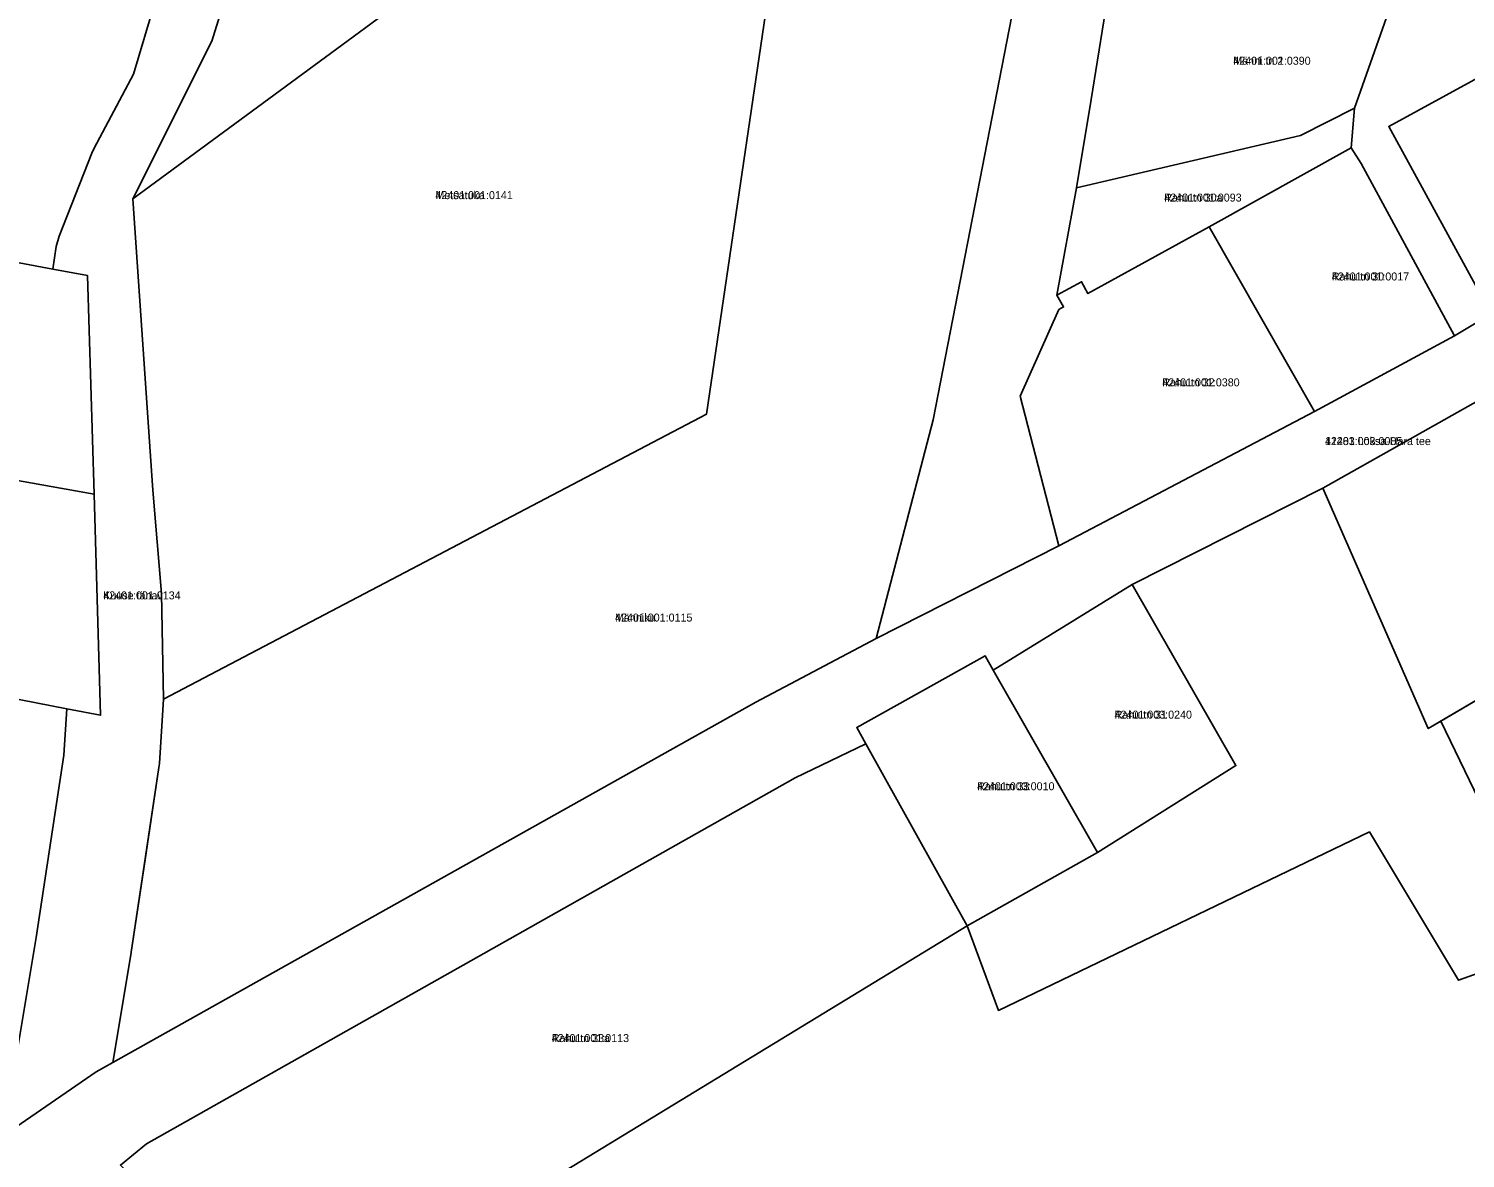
# Model space of a CAD drawing. Extents: x 595979 to 597983, y 6604231 to 6607350.
# Drawn here: x 596596.1 to 596865.4, y 6605070.1 to 6605281.9 of the extents above; entities that cross this region are included whole.
import ezdxf

# ---------------------------------------------------------------- set-up
doc = ezdxf.new("R2010")
doc.units = 0
for name, color, linetype in [('L_AADRESS', 7, 'Continuous'), ('PIIR', 7, 'Continuous'), ('TUNNUS', 7, 'Continuous')]:
    doc.layers.add(name, color=color, linetype=linetype)

msp = doc.modelspace()

# ---------------------------------------------------------------- linework, layer by layer
at = {"layer": 'PIIR'}
for points in [[(596829.27, 6605483.41), (596824.76, 6605453.75), (596820.25, 6605424.09), (596815.74, 6605394.45), (596814.19, 6605387.1), (596809.6, 6605357.21), (596804.47, 6605327.52), (596800, 6605298.23), (596795.25, 6605268.62), (596792.47, 6605252.09), (596788.8, 6605231.98), (596790.07, 6605229.75), (596789.19, 6605229.26), (596781.93, 6605213.04), (596789.19, 6605184.96), (596754.93, 6605167.57), (596765.64, 6605208.57), (596800.12, 6605385.84), (596804.06, 6605408.95), (596828.15, 6605567.17)], [(596647.27, 6605477.41), (596611.18, 6605411.05), (596610.56, 6605409.63), (596605.93, 6605395.9), (596605.48, 6605392.31), (596606.36, 6605381.09), (596607.07, 6605378.23), (596615.3, 6605359.14), (596622.82, 6605323.98), (596624.34, 6605313.37), (596622.34, 6605294.27), (596619.91, 6605287.47), (596619.75, 6605287), (596615.72, 6605273.39), (596608.35, 6605259.53), (596607.93, 6605258.6), (596601.78, 6605243.01), (596601.25, 6605241.06), (596600.61, 6605236.85), (596540.44, 6605248.17)], [(596877.22, 6605277.92), (596851, 6605263.59), (596870.21, 6605228.44), (596863.33, 6605224.33), (596845.82, 6605256.63), (596843.99, 6605259.57), (596844.57, 6605267.01), (596852.1, 6605288.33), (596859, 6605319.44), (596860.74, 6605348.98), (596864.82, 6605379.06), (596814.19, 6605387.1), (596815.74, 6605394.45), (596855.3, 6605388.41), (596859.8, 6605418.07), (596864.31, 6605447.73), (596868.82, 6605477.39)], [(596586.98, 6605071.41), (596608.69, 6605086.35), (596611.84, 6605088.12), (596732.37, 6605155.68), (596754.93, 6605167.57), (596789.19, 6605184.96), (596837.08, 6605210.13), (596863.33, 6605224.33), (596870.21, 6605228.44), (596896.56, 6605243.05), (596922.91, 6605257.44), (596948.6, 6605271.92), (596974.91, 6605286.34), (596986.01, 6605292.19), (596986.85, 6605290.66), (596994.62, 6605294.61), (597013.8, 6605306.51), (597040.14, 6605320.88), (597066.19, 6605334.9), (597093.1, 6605349.19), (597119.27, 6605363.58), (597145.51, 6605378.15), (597174.6, 6605393.75), (597194, 6605402.66)], [(597191.72, 6605387.01), (597156.63, 6605368.74), (597130.33, 6605354.15), (597103, 6605339.04), (597076.68, 6605324.49), (597050.42, 6605309.97), (597024.14, 6605295.52), (597016.87, 6605291.63), (597005.04, 6605285.24), (596978.08, 6605271.56), (596951.16, 6605258.14), (596927.39, 6605245.75), (596904.92, 6605232.87), (596881.66, 6605219.93), (596870.26, 6605213.58), (596838.64, 6605195.76), (596802.93, 6605177.68), (596776.88, 6605161.66), (596775.35, 6605164.36), (596751.28, 6605150.91), (596753, 6605147.82), (596739.75, 6605141.48), (596618.18, 6605072.86), (596613.27, 6605068.86)], [(596635.95, 6605297.46), (596630.39, 6605279.58), (596615.57, 6605250.02), (596619.36, 6605195.41), (596620.94, 6605176.05), (596621.36, 6605156.21), (596620.57, 6605144.18), (596620.49, 6605143.43), (596617.83, 6605125.72), (596615.29, 6605108.8), (596615.27, 6605108.65), (596611.84, 6605088.12), (596608.69, 6605086.35), (596586.98, 6605071.41)], [(596592.87, 6605083.8), (596597.5, 6605111.54), (596602.63, 6605145.74), (596603.2, 6605154.43), (596609.55, 6605153.19), (596608.32, 6605194.62), (596607.1, 6605235.63), (596600.61, 6605236.85), (596601.25, 6605241.06), (596601.78, 6605243.01), (596607.93, 6605258.6), (596608.35, 6605259.53), (596615.72, 6605273.39), (596619.75, 6605287)], [(596927.46, 6605126.04), (596864.06, 6605103.52), (596847.38, 6605131.33), (596777.85, 6605097.85), (596772.01, 6605113.71), (596796.42, 6605127.47), (596822.37, 6605143.75), (596802.93, 6605177.68), (596838.64, 6605195.76), (596858.43, 6605150.7), (596860.75, 6605152.06), (596874.19, 6605124.28)]]:
    msp.add_lwpolyline(points, dxfattribs=at)
for points in [[(596636.26, 6605434.88), (596804.06, 6605408.95), (596800.12, 6605385.84), (596781.86, 6605372.4), (596701.75, 6605313.42), (596615.57, 6605250.02), (596630.39, 6605279.58), (596635.95, 6605297.46), (596636.74, 6605309.9), (596630.78, 6605339.55), (596625.88, 6605356.1), (596620.85, 6605368.15), (596618.6, 6605376.49), (596619.44, 6605389.57), (596622.31, 6605405.35), (596625.22, 6605413.29)], [(596611.84, 6605088.12), (596615.27, 6605108.65), (596615.29, 6605108.8), (596620.49, 6605143.43), (596620.57, 6605144.18), (596621.36, 6605156.21), (596723.1, 6605209.62), (596742.88, 6605343.7), (596781.86, 6605372.4), (596800.12, 6605385.84), (596765.64, 6605208.57), (596754.93, 6605167.57), (596732.37, 6605155.68)], [(596701.75, 6605313.42), (596742.88, 6605343.7), (596723.1, 6605209.62), (596621.36, 6605156.21), (596620.94, 6605176.05), (596619.36, 6605195.41), (596615.57, 6605250.02)], [(596800, 6605298.23), (596839.35, 6605290.97), (596852.1, 6605288.33), (596844.57, 6605267.01), (596834.44, 6605261.91), (596792.47, 6605252.09), (596795.25, 6605268.62)], [(596870.21, 6605228.44), (596851, 6605263.59), (596877.22, 6605277.92), (596896.56, 6605243.05)], [(596793.43, 6605234.48), (596788.8, 6605231.98), (596792.47, 6605252.09), (596834.44, 6605261.91), (596844.57, 6605267.01), (596843.99, 6605259.57), (596817.33, 6605244.76), (596794.63, 6605232.25)], [(596817.33, 6605244.76), (596843.99, 6605259.57), (596845.82, 6605256.63), (596863.33, 6605224.33), (596837.08, 6605210.13)], [(596608.32, 6605194.62), (596533.65, 6605207.97), (596540.44, 6605248.17), (596600.61, 6605236.85), (596607.1, 6605235.63)], [(596788.8, 6605231.98), (596793.43, 6605234.48), (596794.63, 6605232.25), (596817.33, 6605244.76), (596837.08, 6605210.13), (596789.19, 6605184.96), (596781.93, 6605213.04), (596789.19, 6605229.26), (596790.07, 6605229.75)], [(597074.78, 6605236.74), (597130.93, 6604964.61), (596884.36, 6604783.54), (596826.22, 6604842.59), (596722.52, 6604944.87), (596673.89, 6604997.16), (596676.44, 6605002.97), (596651.51, 6605028.71), (596644.52, 6605036.02), (596772.01, 6605113.71), (596777.85, 6605097.85), (596847.38, 6605131.33), (596864.06, 6605103.52), (596927.46, 6605126.04), (596944.97, 6605092.68), (596998.07, 6605124.37), (597042, 6605209.45)], [(596870.26, 6605213.58), (596893.05, 6605171.06), (596858.43, 6605150.7), (596838.64, 6605195.76)], [(596609.55, 6605153.19), (596603.2, 6605154.43), (596527.12, 6605169.27), (596533.65, 6605207.97), (596608.32, 6605194.62)], [(596776.88, 6605161.66), (596802.93, 6605177.68), (596822.37, 6605143.75), (596796.42, 6605127.47)], [(596893.05, 6605171.06), (596908.41, 6605142.99), (596906.17, 6605141.77), (596874.19, 6605124.28), (596860.75, 6605152.06)], [(596603.2, 6605154.43), (596602.63, 6605145.74), (596597.5, 6605111.54), (596592.87, 6605083.8), (596580.93, 6605086.69), (596580.43, 6605086.79), (596558.43, 6605090.82), (596557.99, 6605090.89), (596527.61, 6605094.92), (596527.45, 6605094.94), (596514.81, 6605096.38), (596527.12, 6605169.27)], [(596796.42, 6605127.47), (596772.01, 6605113.71), (596753, 6605147.82), (596751.28, 6605150.91), (596775.35, 6605164.36), (596776.88, 6605161.66)], [(596772.01, 6605113.71), (596644.52, 6605036.02), (596613.27, 6605068.86), (596618.18, 6605072.86), (596739.75, 6605141.48), (596753, 6605147.82)]]:
    msp.add_lwpolyline(points, close=True, dxfattribs=at)

# ---------------------------------------------------------------- texts
at = {"layer": 'L_AADRESS'}
for s, p in [('Männi tn 2', (596821.87, 6605275.16)), ('Metsatuka', (596672.31, 6605249.96)), ('Rahu tn 30a', (596808.93, 6605249.5)), ('Rahu tn 30', (596840.33, 6605234.71)), ('Rahu tn 32', (596808.56, 6605214.86)), ('11283 Loksa-Hara tee', (596839.05, 6605203.85)), ('Kuuse tänav', (596610.05, 6605174.92)), ('Männiku', (596705.98, 6605170.76)), ('Rahu tn 31', (596799.62, 6605152.56)), ('Rahu tn 33', (596773.85, 6605139.13)), ('Rahu tn 33a', (596694.1, 6605091.92))]:
    msp.add_text(s, height=1.5, dxfattribs=at).set_placement(p)
at = {"layer": 'TUNNUS'}
for s, p in [('42401:001:0390', (596821.87, 6605275.16)), ('42401:001:0141', (596672.31, 6605249.96)), ('42401:001:0093', (596808.93, 6605249.5)), ('42401:001:0017', (596840.33, 6605234.71)), ('42401:001:0380', (596808.56, 6605214.86)), ('42401:003:0005', (596839.05, 6605203.85)), ('42401:001:0134', (596610.05, 6605174.92)), ('42401:001:0115', (596705.98, 6605170.76)), ('42401:003:0240', (596799.62, 6605152.56)), ('42401:003:0010', (596773.85, 6605139.13)), ('42401:001:0113', (596694.1, 6605091.92))]:
    msp.add_text(s, height=1.5, dxfattribs=at).set_placement(p)

doc.saveas('drawing.dxf')
